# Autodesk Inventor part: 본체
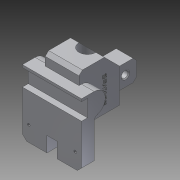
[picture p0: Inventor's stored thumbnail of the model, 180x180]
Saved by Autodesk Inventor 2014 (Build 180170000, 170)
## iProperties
Created: 2016-11
Part Number: 본체
Material: 알루미늄 6061
Document SubType Name: Modeling
Designer: owner
Density: 2.71 g/cm^3
Appearance: 알루미늄 - 평지
Mass: 462.906 g
Surface Area: 317.29 cm^2
Volume: 170.814 cm^3
Author: owner
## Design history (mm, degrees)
sketch "스케치1"
  geometry: L1 (0, 13)-(-15, 13); L2 (-15, 13)-(-15, 10); L3 (-15, 10)-(-8, 10); L4 (-8, 10)-(-8, -10); L5 (-8, -10)-(-15, -10); L6 (-15, -10)-(-15, -63); L7 (-15, -63)-(0, -63); L8 (0, -63)-(0, -13); L9 (-3, 27)-(27, 27); L10 (27, 27)-(45, 9); L11 (45, 9)-(45, -1); L12 (45, -1)-(75, -1); L13 (75, -1)-(75, -26); L14 (75, -26)-(45, -26); L15 (45, -26)-(45, -31); L16 (45, -31)-(5, -31); L17 (5, -31)-(5, -63); L18 (5, -63)-(0, -63); L19 (45, -26)-(45, -1); L20 (-3, 27)-(-3, 13); A1 r 13 centre (0, 0) between (0, -13) and (0, 13); 2 further points
  constraints: 40 end point, 9 parallel, 5 perpendicular, 3 collinear, 3 point on line, 2 point on circle, 1 centre point, 1 coincident, 1 horizontal, 1 tangent
  dimensions: "d1" = 13 radius of A1; "d2" = 15 distance between parallel lines of L6 L8; "d3" = 7 distance of L2.end L3.end; "d4" = 3 distance of L1.end L2.end; "d6" = 20 distance of L3.end L4.end; "d7" = 63 distance from line of point (0, 0) L7; "d8" = 18 distance from line of L9 L10.end; "d9" = 45 deg angle of L9 L10; "d12" = 58 distance between parallel lines of L16 L9; "d13" = 25 distance of L12.end L13.end; "d14" = 5 distance of L14.end L15.end; "d15" = 90 distance between parallel lines of L18 L9; "d16" = 20 distance between parallel lines of L6 L17; "d17" = 90 distance between parallel lines of L6 L13; "d66" = 30 distance from line of L20 L9.end; "d67" = 60 distance between parallel lines of L6 L11
extrude "돌출1" new body sketch "스케치1" stored distance "d18" = 70; taper "d19" = 0 deg
extrude "돌출2" join sketch "스케치1" stored distance "d20" = 40; taper "d21" = 0 deg
extrude "돌출3" join sketch "스케치1" stored distance "d22" = 20; taper "d23" = 0 deg
sketch "스케치2"
  geometry: L1 (40, 0)-(0, 0) reference; L2 (55, -60)-(-15, -60) reference; 3 further points
  constraints: 1 midpoint, 1 vertical alignment
  dimensions: "d24" = 42 distance from line of L2 point (20, -18)
hole "구멍1" sketch "스케치2" at (20, -18) diameter "d25" = 20; stored, may be unused: countersink angle "d29" = 90 deg, drill point angle "d31" = 118 deg; dims "d26" = 6, "d27" = 29, "d28" = 7, "d30" = 8
sketch "스케치3"
  geometry: L1 (55, 20)-(15, 20) reference; L2 (70, 0)-(0, 0) reference; L3 (70, 15)-(70, 0) reference; L4 (35, 15)-(35, -0.983); L5 (41, 0)-(41, 13.627); L6 (29, 0)-(29, 13.627); C1 r 14.5 at (35, 42) reference; A1 r 29 centre (35, 42) between (16.106, 20) and (29, 13.627); A2 r 29 centre (35, 42) between (41, 13.627) and (53.894, 20)
  constraints: 6 end point, 4 point on circle, 4 point on line, 3 parallel, 2 centre point, 1 coincident, 1 concentric, 1 other
  dimensions: "d34" = 12 distance between parallel lines of L6 L5; "d35" = 29 radius of A2
extrude "돌출4" cut sketch "스케치3" distance "d36" = 18; taper "d37" = 0 deg
sketch "스케치4"
  geometry: L1 (-15, 50)-(0, 50) reference; L2 (-25, -40)-(-45, -40) reference; L3 (-16.106, 32)-(-53.894, 32) reference; L4 (-35, -40)-(-35, 32); 5 further points
  constraints: 2 end point, 2 midpoint, 1 symmetric about line
  dimensions: "d38" = 18 distance from line of L1 point (-7.5, 32); "d39" = 55 diameter of point (-7.5, 32) L4
hole "구멍2" sketch "스케치4" at (-7.5, 32), (-62.5, 32) diameter "d40" = 3.242; stored, may be unused: countersink angle "d44" = 90 deg, drill point angle "d46" = 118 deg; dims "d41" = 6, "d42" = 29, "d43" = 7, "d45" = 8
sketch "스케치5"
  geometry: L1 (26, 75)-(1, 75) reference; L2 (10, -15)-(63, -15) reference; C1 r 4 at (13.5, 62); 2 further points
  constraints: 1 centre point, 1 midpoint, 1 vertical alignment
  dimensions: "d47" = 77 distance from line of L2 C1.centre; "d48" = 8 diameter of C1
extrude "돌출5" cut sketch "스케치5" stored distance "d49" = 18; taper "d50" = 0 deg
sketch "스케치6"
  geometry: L1 (31, 5)-(31, 45) reference; L2 (31, 45)-(-9, 45) reference; 1 further point
  constraints: 1 other
  dimensions: "d51" = 25 distance from line of L1 point (6, 27); "d52" = 18 distance from line of L2 point (6, 27)
feature "엠보싱1" sketch "스케치6" dims "d1" = 13, "d2" = 15, "d3" = 7, "d4" = 3, "d6" = 20, "d7" = 63, "d8" = 18, "d9" = 45 deg, "d12" = 58, "d13" = 25, "d14" = 5, "d15" = 90, "d16" = 20, "d17" = 90, "d20" = 40, "d53" = 0.5, "d54" = 0, "d66" = 30, "d67" = 60
chamfer "모따기1" distance "d55" = 1; stored, may be unused: second distance "d56" = 2, angle "d57" = 45 deg
chamfer "모따기2" distance "d58" = 4; stored, may be unused: second distance "d59" = 2, angle "d60" = 45 deg
fillet "모깎기1" dims "d61" = 5
fillet "모깎기2" dims "d62" = 3
chamfer "모따기3" distance "d63" = 5; stored, may be unused: second distance "d64" = 2, angle "d65" = 45 deg
node "솔리드1"
other parameters: "d33" = 29
